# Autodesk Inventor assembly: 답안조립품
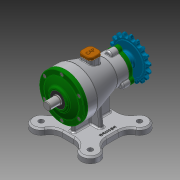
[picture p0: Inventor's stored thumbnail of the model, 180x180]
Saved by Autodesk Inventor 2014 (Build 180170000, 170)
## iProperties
Created: 2018-03
Part Number: 답안조립품
Document SubType Name: Assembly
Designer: kb542
Author: kb542
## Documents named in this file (15)
- C:\Users\kb542\Desktop\480307V1025\답안조립품.iam
- C:\Users\kb542\Desktop\480307V1025\본체.ipt
- C:\Users\kb542\Desktop\480307V1025\뒤커버.ipt
- C:\Users\kb542\Desktop\480307V1025\마개.ipt
- C:\Users\kb542\Desktop\480307V1025\베어링-6200.ipt
- C:\Users\kb542\Desktop\480307V1025\베어링-6203.ipt
- C:\Users\kb542\Desktop\480307V1025\볼트 M4 x 12.ipt
- 볼트 M4 x 12.ipt
- C:\Users\kb542\Desktop\480307V1025\스프로킷.ipt
- C:\Users\kb542\Desktop\480307V1025\앞커버.ipt
- C:\Users\kb542\Desktop\480307V1025\오일 실 10 20 7.ipt
- C:\Users\kb542\Desktop\480307V1025\오일 실 17 30 8.ipt
- C:\Users\kb542\Desktop\480307V1025\축.ipt
- C:\Users\kb542\Desktop\480307V1025\키 5 x 5.ipt
- 키 5 x 5.ipt
